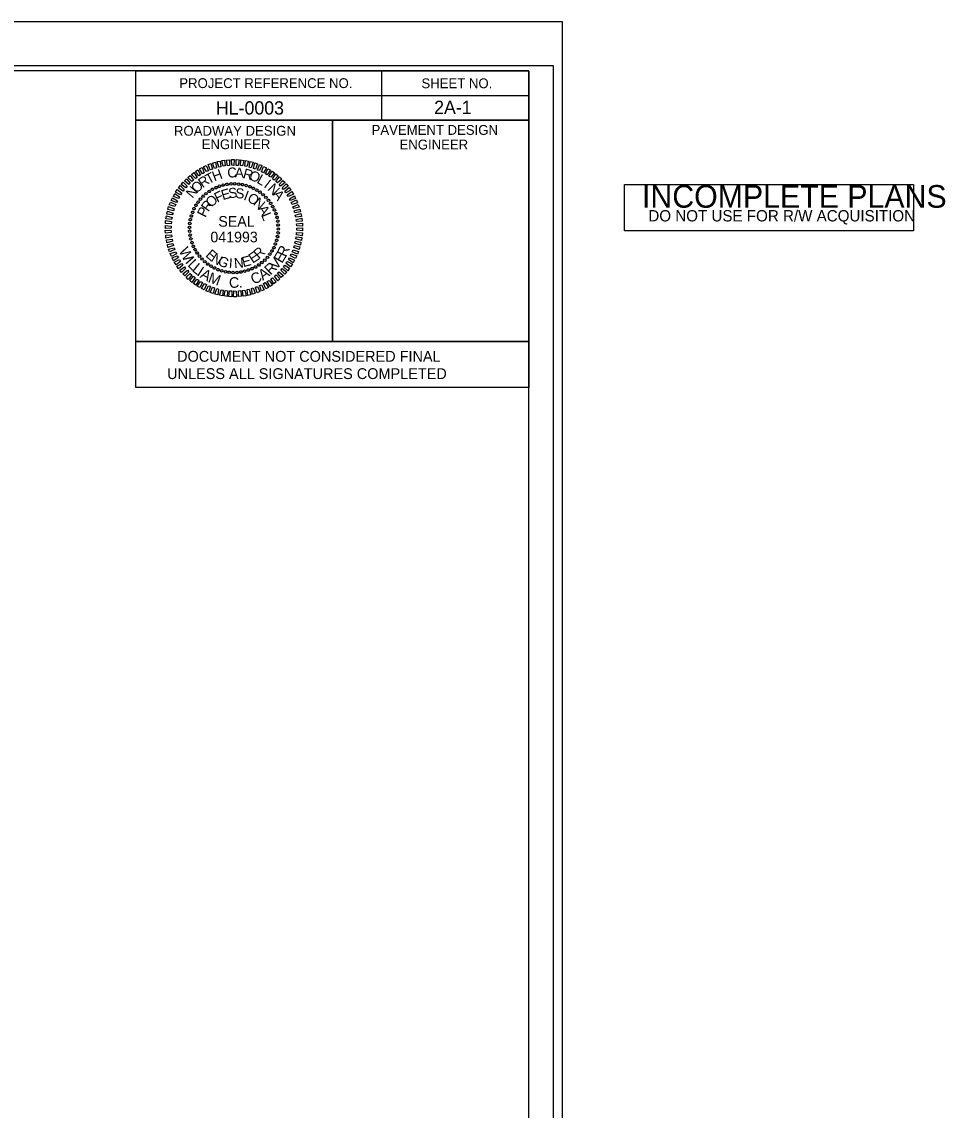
# Model space of a CAD drawing. Extents: x 1022283 to 1026986, y 174822 to 180471.
# Drawn here: x 1025806 to 1026980, y 179087 to 180471 of the extents above; entities that cross this region are included whole.
import ezdxf

# ---------------------------------------------------------------- set-up
doc = ezdxf.new("R2010")
doc.units = 0
for name, color, linetype in [('Default', 7, 'Continuous'), ('Sheet Cutting Line CELL', 7, 'Continuous'), ('Sheet Data Field CELL', 7, 'Continuous'), ('Sheet Plot Border Inside CELL', 7, 'Continuous'), ('Sheet Plot Border Outside CELL', 7, 'Continuous'), ('Sheet Sticker Exception Certification CELL', 7, 'Continuous'), ('Sheet Sticker Incomplete CELL', 7, 'Continuous'), ('Sheet Typical CELL', 7, 'Continuous')]:
    doc.layers.add(name, color=color, linetype=linetype)

msp = doc.modelspace()

# ---------------------------------------------------------------- linework, layer by layer
at = {"layer": 'Default'}
for p, q in [((1026040, 180253), (1026040, 180253)), ((1026043.9, 180255.8), (1026043.9, 180255.8)), ((1026048.2, 180258.4), (1026048.2, 180258.4)), ((1026052.6, 180260.7), (1026052.6, 180260.7)), ((1026057.1, 180262.5), (1026057.1, 180262.5)), ((1026061.8, 180263.8), (1026061.8, 180263.8)), ((1026066.8, 180264.7), (1026066.8, 180264.7)), ((1026071.6, 180265.4), (1026071.6, 180265.4)), ((1026076.6, 180265.5), (1026076.6, 180265.5)), ((1026081.5, 180265.2), (1026081.5, 180265.2)), ((1026086.3, 180264.4), (1026086.3, 180264.4)), ((1026091.1, 180263.4), (1026091.1, 180263.4)), ((1026095.8, 180261.8), (1026095.8, 180261.8)), ((1026100.3, 180259.8), (1026100.3, 180259.8)), ((1026104.7, 180257.5), (1026104.7, 180257.5)), ((1026108.7, 180254.7), (1026108.7, 180254.7)), ((1026029.9, 180242.2), (1026029.9, 180242.2)), ((1026032.9, 180246.2), (1026032.9, 180246.2)), ((1026036.3, 180249.6), (1026036.3, 180249.6)), ((1026112.7, 180251.7), (1026112.7, 180251.7)), ((1026116.2, 180248.3), (1026116.2, 180248.3)), ((1026119.5, 180244.6), (1026119.5, 180244.6)), ((1026122.3, 180240.6), (1026122.3, 180240.6)), ((1026022.8, 180229.3), (1026022.8, 180229.3)), ((1026024.8, 180233.8), (1026024.8, 180233.8)), ((1026027.1, 180238.2), (1026027.1, 180238.2)), ((1026124.9, 180236.4), (1026124.9, 180236.4)), ((1026127.2, 180232), (1026127.2, 180232)), ((1026129, 180227.5), (1026129, 180227.5)), ((1026019.4, 180215), (1026019.4, 180215)), ((1026020.2, 180219.8), (1026020.2, 180219.8)), ((1026021.2, 180224.6), (1026021.2, 180224.6)), ((1026130.3, 180222.8), (1026130.3, 180222.8)), ((1026131.2, 180217.8), (1026131.2, 180217.8)), ((1026131.9, 180213), (1026131.9, 180213)), ((1026019.1, 180210), (1026019.1, 180210)), ((1026019.2, 180205.1), (1026019.2, 180205.1)), ((1026019.9, 180200.3), (1026019.9, 180200.3)), ((1026075.5, 180209), (1026075.5, 180209)), ((1026130.9, 180198.2), (1026130.9, 180198.2)), ((1026131.7, 180203.1), (1026131.7, 180203.1)), ((1026132, 180208), (1026132, 180208)), ((1026020.8, 180195.3), (1026020.8, 180195.3)), ((1026022.1, 180190.6), (1026022.1, 180190.6)), ((1026023.9, 180186.1), (1026023.9, 180186.1)), ((1026126.3, 180184.3), (1026126.3, 180184.3)), ((1026128.3, 180188.8), (1026128.3, 180188.8)), ((1026129.9, 180193.5), (1026129.9, 180193.5)), ((1026026.2, 180181.7), (1026026.2, 180181.7)), ((1026028.7, 180177.4), (1026028.7, 180177.4)), ((1026031.6, 180173.5), (1026031.6, 180173.5)), ((1026118.2, 180171.9), (1026118.2, 180171.9)), ((1026121.2, 180175.8), (1026121.2, 180175.8)), ((1026124, 180179.9), (1026124, 180179.9)), ((1026034.9, 180169.8), (1026034.9, 180169.8)), ((1026038.4, 180166.4), (1026038.4, 180166.4)), ((1026042.4, 180163.4), (1026042.4, 180163.4)), ((1026046.4, 180160.5), (1026046.4, 180160.5)), ((1026050.8, 180158.3), (1026050.8, 180158.3)), ((1026055.3, 180156.3), (1026055.3, 180156.3)), ((1026098.5, 180157.4), (1026098.5, 180157.4)), ((1026102.9, 180159.6), (1026102.9, 180159.6)), ((1026107.2, 180162.2), (1026107.2, 180162.2)), ((1026111.1, 180165), (1026111.1, 180165)), ((1026114.8, 180168.4), (1026114.8, 180168.4)), ((1026060, 180154.7), (1026060, 180154.7)), ((1026064.7, 180153.7), (1026064.7, 180153.7)), ((1026069.6, 180152.9), (1026069.6, 180152.9)), ((1026074.5, 180152.6), (1026074.5, 180152.6)), ((1026079.5, 180152.7), (1026079.5, 180152.7)), ((1026084.3, 180153.3), (1026084.3, 180153.3)), ((1026089.3, 180154.2), (1026089.3, 180154.2)), ((1026094, 180155.6), (1026094, 180155.6))]:
    msp.add_line(p, q, dxfattribs=at)
for points in [[(1026056.4, 180286.5), (1026054.1, 180293.6), (1026057.9, 180294.4), (1026058.8, 180287.1)], [(1026061.8, 180287.8), (1026060, 180295), (1026063.7, 180295.3), (1026064.5, 180288.1)], [(1026067.2, 180288.5), (1026066, 180295.7), (1026069.8, 180296.1), (1026069.9, 180288.8)], [(1026072.8, 180289), (1026072.3, 180296.3), (1026076, 180296.2), (1026075.5, 180288.9)], [(1026078.2, 180288.9), (1026078.2, 180296.2), (1026082, 180296.1), (1026080.9, 180288.8)], [(1026083.9, 180288.6), (1026084.3, 180295.9), (1026088, 180295.2), (1026086.6, 180288.1)], [(1026089.3, 180287.7), (1026090.3, 180294.9), (1026094, 180294.3), (1026092, 180287.3)], [(1026030.8, 180275.4), (1026026.6, 180281.1), (1026029.5, 180283.3), (1026033.2, 180276.8)], [(1026035.7, 180278.2), (1026031.6, 180284.3), (1026035, 180286.1), (1026037.9, 180279.6)], [(1026040.6, 180280.9), (1026037, 180287.2), (1026040.4, 180288.8), (1026043, 180281.9)], [(1026045.5, 180283.3), (1026042.6, 180289.8), (1026046, 180291.2), (1026048.3, 180284)], [(1026051, 180285.1), (1026048.4, 180291.8), (1026051.9, 180292.8), (1026053.4, 180285.9)], [(1026095, 180286.4), (1026096.1, 180293.7), (1026100, 180292.8), (1026097.4, 180285.9)], [(1026100.4, 180285), (1026102.1, 180291.9), (1026105.6, 180290.8), (1026102.8, 180284.2)], [(1026105.5, 180282.9), (1026108.1, 180290), (1026111.2, 180288.7), (1026108.1, 180282.2)], [(1026110.5, 180280.8), (1026113.3, 180287.4), (1026116.8, 180285.9), (1026113, 180279.6)], [(1026115.7, 180278.2), (1026118.7, 180284.6), (1026122.1, 180282.7), (1026117.8, 180276.9)], [(1026120.1, 180275.2), (1026124, 180281.7), (1026127, 180279.3), (1026122.6, 180273.8)], [(1026014.3, 180260.3), (1026008.5, 180264.7), (1026011, 180267.6), (1026015.9, 180262.4)], [(1026018.3, 180264.6), (1026012.5, 180269.2), (1026015.4, 180271.8), (1026020.1, 180266.4)], [(1026022, 180268.5), (1026017, 180273.5), (1026019.7, 180276.2), (1026024.1, 180270.1)], [(1026026.5, 180272), (1026021.7, 180277.4), (1026024.7, 180279.8), (1026028.6, 180273.5)], [(1026124.7, 180271.8), (1026128.9, 180278), (1026131.8, 180275.5), (1026126.8, 180270.2)], [(1026129, 180268.3), (1026133.6, 180274.2), (1026136.3, 180271.5), (1026131.1, 180266.6)], [(1026133, 180264.4), (1026137.9, 180269.7), (1026140.6, 180267), (1026134.7, 180262.6)], [(1026004.9, 180246.7), (1025998.5, 180249.5), (1026000.2, 180253), (1026006.2, 180248.9)], [(1026007.6, 180251.6), (1026001.3, 180254.9), (1026003.5, 180258.1), (1026009.4, 180253.6)], [(1026011, 180256.1), (1026004.9, 180259.9), (1026007, 180263.1), (1026012.4, 180258.2)], [(1026137, 180260.3), (1026142.1, 180265.4), (1026144.5, 180262.4), (1026138.5, 180258.1)], [(1026140.3, 180255.9), (1026145.9, 180260.7), (1026148, 180257.4), (1026141.7, 180253.8)], [(1026143.3, 180251.3), (1026149.2, 180255.6), (1026151.4, 180252.2), (1026144.8, 180249.1)], [(1026000.4, 180236.6), (1025993.4, 180238.6), (1025994.9, 180242.1), (1026001.6, 180239)], [(1026002.6, 180241.5), (1025995.7, 180244.1), (1025997.4, 180247.6), (1026003.8, 180244)], [(1026146.2, 180246.4), (1026152.5, 180250.3), (1026154, 180246.8), (1026147.5, 180244.2)], [(1026148.4, 180241.5), (1026155.1, 180244.9), (1026156.5, 180241.3), (1026149.6, 180239.1)], [(1026150.5, 180236.3), (1026157.3, 180239.2), (1026158.6, 180235.7), (1026151.6, 180233.9)], [(1025997.2, 180225.8), (1025990.3, 180226.7), (1025991.1, 180230.5), (1025998.1, 180228.2)], [(1025998.7, 180231.2), (1025991.7, 180232.7), (1025992.5, 180236.4), (1025999.6, 180233.6)], [(1026152.3, 180230.9), (1026159.5, 180233.4), (1026160.1, 180229.7), (1026153.1, 180228.5)], [(1026153.6, 180225.5), (1026160.7, 180227.6), (1026161.4, 180223.8), (1026154.3, 180223.1)], [(1025995.7, 180209), (1025988.4, 180208.7), (1025988.4, 180212.5), (1025995.7, 180211.7)], [(1025995.8, 180214.7), (1025988.5, 180214.9), (1025988.7, 180218.6), (1025996, 180217.4)], [(1025996.3, 180220.1), (1025989.1, 180220.7), (1025989.6, 180224.6), (1025996.9, 180222.8)], [(1026154.6, 180220.1), (1026161.9, 180221.6), (1026162.3, 180217.8), (1026155.1, 180217.4)], [(1026155.3, 180214.7), (1026162.6, 180215.6), (1026162.8, 180211.7), (1026155.5, 180212)], [(1025995.8, 180203.4), (1025988.5, 180202.5), (1025988.2, 180206.3), (1025995.6, 180206.1)], [(1025996.5, 180198), (1025989.1, 180196.4), (1025988.8, 180200.3), (1025996, 180200.7)], [(1026154.7, 180198), (1026161.9, 180197.3), (1026161.5, 180193.5), (1026154.2, 180195.3)], [(1026155.3, 180203.4), (1026162.6, 180203.2), (1026162.4, 180199.5), (1026155.1, 180200.7)], [(1026155.4, 180209), (1026162.7, 180209.4), (1026162.7, 180205.5), (1026155.4, 180206.3)], [(1025997.5, 180192.6), (1025990.4, 180190.5), (1025989.7, 180194.3), (1025996.8, 180195)], [(1025998.8, 180187.2), (1025991.6, 180184.6), (1025990.9, 180188.3), (1025998, 180189.6)], [(1026000.6, 180181.8), (1025993.8, 180178.9), (1025992.5, 180182.4), (1025999.5, 180184.2)], [(1026152.4, 180186.9), (1026159.4, 180185.4), (1026158.6, 180181.7), (1026151.5, 180184.5)], [(1026153.8, 180192.3), (1026160.8, 180191.4), (1026160, 180187.5), (1026152.9, 180189.9)], [(1026002.6, 180176.5), (1025996, 180173.1), (1025994.5, 180176.7), (1026001.5, 180179)], [(1026004.9, 180171.7), (1025998.6, 180167.7), (1025997.1, 180171.2), (1026003.5, 180173.8)], [(1026146.2, 180171.3), (1026152.6, 180168.5), (1026150.9, 180165), (1026144.8, 180169.2)], [(1026148.4, 180176.5), (1026155.4, 180173.9), (1026153.7, 180170.4), (1026147.3, 180174)], [(1026150.7, 180181.5), (1026157.7, 180179.4), (1026156.2, 180176), (1026149.5, 180179.1)], [(1026007.8, 180166.7), (1026001.9, 180162.5), (1025999.7, 180165.8), (1026006.2, 180169)], [(1026010.7, 180162.1), (1026005.2, 180157.4), (1026003.1, 180160.7), (1026009.4, 180164.3)], [(1026014.1, 180157.7), (1026008.9, 180152.7), (1026006.6, 180155.7), (1026012.5, 180160)], [(1026136.7, 180157.7), (1026142.6, 180153.3), (1026140.1, 180150.4), (1026135.2, 180155.7)], [(1026140.1, 180162), (1026146.2, 180158.2), (1026144.1, 180154.9), (1026138.7, 180159.9)], [(1026143.5, 180166.5), (1026149.8, 180163.1), (1026147.5, 180160), (1026141.7, 180164.5)], [(1026018.1, 180153.7), (1026013.2, 180148.4), (1026010.5, 180151.1), (1026016.4, 180155.5)], [(1026022.1, 180149.7), (1026017.5, 180143.9), (1026014.8, 180146.6), (1026020, 180151.4)], [(1026026.4, 180146.3), (1026022.2, 180140.1), (1026019.3, 180142.5), (1026024.2, 180147.8)], [(1026031, 180142.9), (1026027.1, 180136.4), (1026024.1, 180138.7), (1026028.5, 180144.2)], [(1026120.3, 180142.7), (1026124.5, 180136.9), (1026121.6, 180134.8), (1026117.8, 180141.3)], [(1026124.6, 180146), (1026129.4, 180140.6), (1026126.4, 180138.3), (1026122.5, 180144.6)], [(1026129.1, 180149.5), (1026134, 180144.6), (1026131.3, 180141.9), (1026127, 180147.9)], [(1026132.8, 180153.5), (1026138.5, 180148.8), (1026135.7, 180146.3), (1026131, 180151.7)], [(1026035.4, 180139.8), (1026032.3, 180133.4), (1026029, 180135.3), (1026033.2, 180141.2)], [(1026040.6, 180137.3), (1026037.7, 180130.6), (1026034.3, 180132.2), (1026038.1, 180138.5)], [(1026045.6, 180135.1), (1026043, 180128), (1026039.9, 180129.4), (1026043, 180135.9)], [(1026050.7, 180133.1), (1026049, 180126.1), (1026045.5, 180127.2), (1026048.3, 180133.9)], [(1026056.1, 180131.6), (1026055, 180124.3), (1026051.1, 180125.2), (1026053.7, 180132.2)], [(1026061.8, 180130.4), (1026060.8, 180123.2), (1026057.1, 180123.8), (1026059.1, 180130.7)], [(1026067.2, 180129.5), (1026066.8, 180122.2), (1026063.1, 180122.9), (1026064.5, 180129.9)], [(1026072.8, 180129.2), (1026072.8, 180121.8), (1026069.1, 180122), (1026070.1, 180129.3)], [(1026078.2, 180129), (1026078.8, 180121.7), (1026075.1, 180121.8), (1026075.5, 180129.2)], [(1026083.9, 180129.6), (1026085.1, 180122.4), (1026081.3, 180122), (1026081.2, 180129.3)], [(1026089.3, 180130.3), (1026091.1, 180123.1), (1026087.4, 180122.7), (1026086.6, 180129.9)], [(1026094.7, 180131.5), (1026097, 180124.4), (1026093.2, 180123.6), (1026092.3, 180131)], [(1026100.1, 180133), (1026102.7, 180126.2), (1026099.2, 180125.2), (1026097.7, 180132.2)], [(1026105.6, 180134.8), (1026108.5, 180128.3), (1026105.1, 180126.9), (1026102.8, 180134.1)], [(1026110.5, 180137.1), (1026114.1, 180130.8), (1026110.6, 180129.3), (1026108.1, 180136.1)], [(1026115.4, 180139.8), (1026119.5, 180133.8), (1026116, 180132), (1026113.2, 180138.5)]]:
    msp.add_lwpolyline(points, close=True, dxfattribs=at)
for centre, major_axis in [((1026071.6, 180265.3), (-0.11, 1.62)), ((1026076.5, 180265.4), (0.03, 1.62)), ((1026081.4, 180265.1), (0.17, 1.61)), ((1026040, 180252.9), (-1.02, 1.26)), ((1026044, 180255.8), (-0.91, 1.34)), ((1026048.2, 180258.4), (-0.79, 1.42)), ((1026052.6, 180260.6), (-0.66, 1.48)), ((1026057.2, 180262.4), (-0.53, 1.53)), ((1026061.9, 180263.8), (-0.39, 1.57)), ((1026066.7, 180264.8), (-0.25, 1.6)), ((1026086.3, 180264.4), (0.31, 1.59)), ((1026091.1, 180263.3), (0.45, 1.56)), ((1026095.8, 180261.7), (0.58, 1.51)), ((1026100.3, 180259.7), (0.71, 1.46)), ((1026104.6, 180257.4), (0.83, 1.39)), ((1026108.7, 180254.7), (0.95, 1.31)), ((1026112.6, 180251.6), (1.06, 1.22)), ((1026027.2, 180238.1), (-1.39, 0.83)), ((1026029.9, 180242.2), (-1.31, 0.95)), ((1026033, 180246), (-1.22, 1.06)), ((1026036.3, 180249.6), (-1.13, 1.17)), ((1026116.1, 180248.2), (1.17, 1.13)), ((1026119.4, 180244.5), (1.26, 1.02)), ((1026122.3, 180240.6), (1.34, 0.91)), ((1026021.3, 180224.6), (-1.56, 0.45)), ((1026022.9, 180229.3), (-1.51, 0.58)), ((1026024.8, 180233.8), (-1.46, 0.71)), ((1026124.9, 180236.4), (1.42, 0.79)), ((1026127.1, 180232), (1.48, 0.66)), ((1026128.9, 180227.4), (1.53, 0.53)), ((1026019.1, 180210), (-1.62, 0.03)), ((1026019.4, 180214.9), (-1.61, 0.17)), ((1026020.1, 180219.8), (-1.59, 0.31)), ((1026130.3, 180222.7), (1.57, 0.39)), ((1026131.3, 180217.9), (1.6, 0.25)), ((1026131.8, 180213), (1.62, 0.11)), ((1026019.2, 180205.1), (-1.62, -0.11)), ((1026019.8, 180200.2), (-1.6, -0.25)), ((1026130.9, 180198.3), (1.59, -0.31)), ((1026131.7, 180203.1), (1.61, -0.17)), ((1026132, 180208), (1.62, -0.03)), ((1026020.8, 180195.4), (-1.57, -0.39)), ((1026022.2, 180190.7), (-1.53, -0.53)), ((1026024, 180186.1), (-1.48, -0.66)), ((1026126.3, 180184.3), (1.46, -0.71)), ((1026128.2, 180188.8), (1.51, -0.58)), ((1026129.8, 180193.5), (1.56, -0.45)), ((1026026.2, 180181.7), (-1.42, -0.79)), ((1026028.8, 180177.5), (-1.34, -0.91)), ((1026031.7, 180173.5), (-1.26, -1.02)), ((1026034.9, 180169.8), (-1.17, -1.13)), ((1026114.7, 180168.4), (1.13, -1.17)), ((1026118.1, 180172), (1.22, -1.06)), ((1026121.2, 180175.9), (1.31, -0.95)), ((1026123.9, 180180), (1.39, -0.83)), ((1026038.5, 180166.4), (-1.06, -1.22)), ((1026042.4, 180163.4), (-0.95, -1.31)), ((1026046.5, 180160.7), (-0.83, -1.39)), ((1026050.8, 180158.3), (-0.71, -1.46)), ((1026055.3, 180156.3), (-0.58, -1.51)), ((1026060, 180154.8), (-0.45, -1.56)), ((1026089.2, 180154.3), (0.39, -1.57)), ((1026093.9, 180155.7), (0.53, -1.53)), ((1026098.5, 180157.5), (0.66, -1.48)), ((1026102.9, 180159.7), (0.79, -1.42)), ((1026107.1, 180162.2), (0.91, -1.34)), ((1026111.1, 180165.2), (1.02, -1.26)), ((1026064.8, 180153.6), (-0.31, -1.59)), ((1026069.6, 180152.9), (-0.17, -1.61)), ((1026074.6, 180152.6), (-0.03, -1.62)), ((1026079.5, 180152.7), (0.11, -1.62)), ((1026084.4, 180153.3), (0.25, -1.6))]:
    msp.add_ellipse(centre, major_axis=major_axis, ratio=0.999708, dxfattribs=at)
at = {"layer": 'Sheet Cutting Line CELL'}
msp.add_line((1026493.2, 180471.5), (1022283.2, 180471.5), dxfattribs=at)
at = {"layer": 'Sheet Plot Border Inside CELL'}
msp.add_lwpolyline([(1026482, 180415.4), (1022315.7, 180415.4), (1022315.7, 177777.6), (1026482, 177777.6)], close=True, dxfattribs=at)
at = {"layer": 'Sheet Plot Border Outside CELL'}
msp.add_lwpolyline([(1026493.2, 180471.5), (1022283.2, 180471.5), (1022283.2, 177721.5), (1026493.2, 177721.5)], close=True, dxfattribs=at)
at = {"layer": 'Sheet Sticker Exception Certification CELL'}
for p, q in [((1025950.6, 180006.4), (1025950.6, 180065.1)), ((1025950.6, 180065.1), (1026450.7, 180065.1)), ((1026450.7, 180065.1), (1026450.7, 180006.3)), ((1026450.7, 180006.4), (1025950.6, 180006.4))]:
    msp.add_line(p, q, dxfattribs=at)
at = {"layer": 'Sheet Sticker Incomplete CELL'}
msp.add_lwpolyline([(1026572, 180205.7), (1026572, 180264.5), (1026939.5, 180264.5), (1026939.5, 180205.7)], close=True, dxfattribs=at)
at = {"layer": 'Sheet Typical CELL'}
for p, q in [((1026263.2, 180408.9), (1026263.2, 180346.4)), ((1025950.6, 180377.6), (1026450.7, 180377.6)), ((1026200.7, 180346.4), (1026200.7, 180065.2))]:
    msp.add_line(p, q, dxfattribs=at)
for points in [[(1026450.7, 180409), (1022700.7, 180409), (1022700.7, 177784), (1026450.7, 177784)], [(1025950.6, 180409), (1026450.7, 180409), (1026450.7, 180346.4), (1025950.6, 180346.4)], [(1025950.6, 180346.4), (1026200.7, 180346.4), (1026200.7, 180065.1), (1025950.6, 180065.1)], [(1026200.7, 180346.4), (1026450.7, 180346.4), (1026450.7, 180065.1), (1026200.7, 180065.1)]]:
    msp.add_lwpolyline(points, close=True, dxfattribs=at)

# ---------------------------------------------------------------- texts
at = {"layer": 'Default'}
for s, height, rotation, p in [('H', 12.7, 20.6195, (1026050.7, 180268.3)), ('C', 12.7, 6.2199, (1026067.8, 180272.8)), ('A', 12.7, 359.0203, (1026076.7, 180273.5)), ('R', 12.7, 344.6211, (1026086.1, 180273)), ('O', 12.7, 337.4212, (1026093.7, 180271.4)), ('O', 12.7, 42.2217, (1026028, 180252.7)), ('R', 12.7, 35.0205, (1026035.7, 180259.7)), ('T', 12.7, 27.8198, (1026043.4, 180264.6)), ('L', 12.7, 330.2209, (1026103.6, 180267.2)), ('I', 12.7, 323.0201, (1026112.7, 180261.8)), ('N', 12.7, 49.4235, (1026022.8, 180246.2)), ('F', 12.7, 25.967, (1026054.3, 180241.2)), ('E', 12.7, 16.6111, (1026061.5, 180244.6)), ('S', 12.7, 7.2556, (1026069.2, 180246.9)), ('S', 12.7, 357.9004, (1026077.3, 180247.1)), ('I', 12.7, 339.1896, (1026087, 180245.5)), ('O', 12.7, 329.8335, (1026091.5, 180243.9)), ('N', 12.7, 315.8189, (1026117.5, 180258.3)), ('A', 12.7, 308.6172, (1026124.1, 180251.7)), ('R', 12.7, 54.0397, (1026042.9, 180229.1)), ('O', 12.7, 44.6812, (1026046.9, 180234.6)), ('N', 12.7, 320.4766, (1026099.1, 180239.4)), ('P', 12.7, 63.3989, (1026039.3, 180221.9)), ('A', 12.7, 301.7603, (1026105.5, 180233.6)), ('L', 12.7, 292.4008, (1026109.9, 180225.8)), ('SEAL', 13.5, 360, (1026055.7, 180210.9)), ('W', 13.5, 298.3574, (1026004.9, 180180.3)), ('R', 12.7, 42.4814, (1026107.3, 180169.1)), ('R', 13.5, 66.6964, (1026141.9, 180171.4)), ('I', 13.5, 310.8915, (1026012.8, 180165.7)), ('L', 13.5, 314.6934, (1026015.8, 180161.6)), ('E', 12.7, 318.2769, (1026038.6, 180173.8)), ('N', 12.7, 327.634, (1026045.4, 180167.7)), ('G', 12.7, 336.9902, (1026053.9, 180162.7)), ('I', 12.7, 355.7012, (1026068.7, 180158.4)), ('N', 12.7, 5.0564, (1026076.2, 180158.1)), ('E', 12.7, 14.4118, (1026087.4, 180159.4)), ('E', 12.7, 33.1241, (1026099.3, 180163.8)), ('V', 13.5, 51.3341, (1026129.6, 180155.2)), ('E', 13.5, 59.5871, (1026136.7, 180163.5)), ('L', 13.5, 320.9682, (1026021.3, 180155.3)), ('I', 13.5, 327.2429, (1026027.5, 180149.7)), ('A', 13.5, 331.0449, (1026031.6, 180146.7)), ('A', 13.5, 35.0135, (1026112.3, 180142.2)), ('R', 13.5, 43.8538, (1026122.1, 180148.6)), ('M', 13.5, 339.8852, (1026041.7, 180140.7)), ('C', 13.5, 1.6151, (1026069.4, 180133)), ('C', 13.5, 25.4313, (1026100.6, 180137)), ('.', 13.5, 11.1972, (1026082.1, 180133))]:
    msp.add_text(s, height=height, rotation=rotation, dxfattribs=at).set_placement(p)
msp.add_text('041993', height=13.5, dxfattribs=at).set_placement((1026045.6, 180191))
at = {"layer": 'Sheet Data Field CELL'}
for s, p in [('HL-0003', (1026052.6, 180353.5)), ('2A-1', (1026330.1, 180354.2))]:
    msp.add_text(s, height=16.88, dxfattribs=at).set_placement(p)
at = {"layer": 'Sheet Sticker Exception Certification CELL'}
for s, p in [('DOCUMENT NOT CONSIDERED FINAL', (1026003.3, 180039.2)), ('UNLESS ALL SIGNATURES COMPLETED', (1025990.6, 180017.2))]:
    msp.add_text(s, height=13.75, dxfattribs=at).set_placement(p)
at = {"layer": 'Sheet Sticker Incomplete CELL'}
for s, height, p in [('INCOMPLETE PLANS', 28.8, (1026594.4, 180235)), ('DO NOT USE FOR R/W ACQUISITION', 14.4, (1026602.5, 180217.6))]:
    msp.add_text(s, height=height, dxfattribs=at).set_placement(p)
at = {"layer": 'Sheet Typical CELL'}
for s, p in [('PROJECT REFERENCE NO.', (1026006.1, 180387.2)), ('SHEET NO.', (1026314, 180387)), ('ROADWAY DESIGN', (1025999.3, 180326.6)), ('PAVEMENT DESIGN', (1026250.6, 180327.7)), ('ENGINEER', (1026034.5, 180309.5)), ('ENGINEER', (1026286.1, 180309.1))]:
    msp.add_text(s, height=12.5, dxfattribs=at).set_placement(p)

doc.saveas('drawing.dxf')
